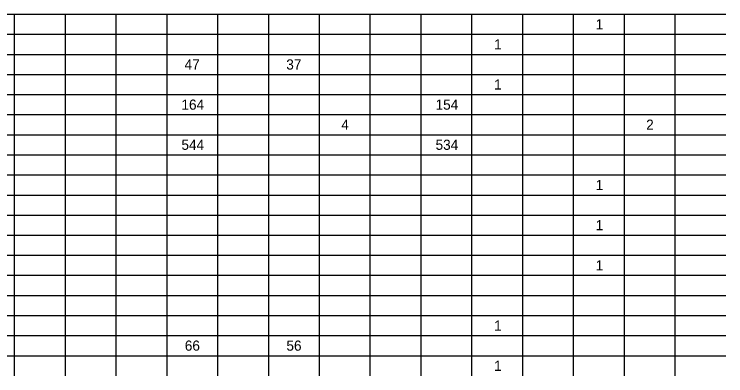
# Model space of a CAD drawing. Extents: x 0 to 34, y 0 to 22.
# Drawn here: x 16.82 to 26.95, y 10.33 to 15.49 of the extents above; entities that cross this region are included whole.
import ezdxf

# ---------------------------------------------------------------- set-up
doc = ezdxf.new("R2010")
doc.units = 0
doc.layers.add('Default', color=7, linetype='Continuous')

msp = doc.modelspace()

# ---------------------------------------------------------------- linework, layer by layer
at = {"layer": 'Default'}
for p, q in [((15.374, 15.486), (16.822, 15.486)), ((16.822, 15.486), (23.336, 15.486)), ((16.822, 15.486), (16.822, 15.199)), ((17.546, 15.486), (17.546, 15.199)), ((18.27, 15.486), (18.27, 15.199)), ((18.993, 15.486), (18.993, 15.199)), ((19.717, 15.486), (19.717, 15.199)), ((20.441, 15.486), (20.441, 15.199)), ((21.165, 15.486), (21.165, 15.199)), ((21.888, 15.486), (21.888, 15.199)), ((22.612, 15.486), (22.612, 15.199)), ((23.336, 15.486), (24.06, 15.486)), ((23.336, 15.486), (23.336, 15.199)), ((24.06, 15.486), (26.231, 15.486)), ((24.06, 15.486), (24.06, 15.199)), ((24.783, 15.486), (24.783, 15.199)), ((25.507, 15.486), (25.507, 15.199)), ((26.231, 15.486), (26.955, 15.486)), ((26.231, 15.486), (26.231, 15.199)), ((15.374, 15.199), (16.822, 15.199)), ((16.822, 15.199), (23.336, 15.199)), ((16.822, 15.199), (16.822, 14.913)), ((17.546, 15.199), (17.546, 14.913)), ((18.27, 15.199), (18.27, 14.913)), ((18.993, 15.199), (18.993, 14.913)), ((19.717, 15.199), (19.717, 14.913)), ((20.441, 15.199), (20.441, 14.913)), ((21.165, 15.199), (21.165, 14.913)), ((21.888, 15.199), (21.888, 14.913)), ((22.612, 15.199), (22.612, 14.913)), ((23.336, 15.199), (24.06, 15.199)), ((23.336, 15.199), (23.336, 14.913)), ((24.06, 15.199), (26.231, 15.199)), ((24.06, 15.199), (24.06, 14.913)), ((24.783, 15.199), (24.783, 14.913)), ((25.507, 15.199), (25.507, 14.913)), ((26.231, 15.199), (26.955, 15.199)), ((26.231, 15.199), (26.231, 14.913)), ((15.374, 14.913), (16.822, 14.913)), ((16.822, 14.913), (23.336, 14.913)), ((16.822, 14.913), (16.822, 14.626)), ((17.546, 14.913), (17.546, 14.626)), ((18.27, 14.913), (18.27, 14.626)), ((18.993, 14.913), (18.993, 14.626)), ((19.717, 14.913), (19.717, 14.626)), ((20.441, 14.913), (20.441, 14.626)), ((21.165, 14.913), (21.165, 14.626)), ((21.888, 14.913), (21.888, 14.626)), ((22.612, 14.913), (22.612, 14.626)), ((23.336, 14.913), (24.06, 14.913)), ((23.336, 14.913), (23.336, 14.626)), ((24.06, 14.913), (26.231, 14.913)), ((24.06, 14.913), (24.06, 14.626)), ((24.783, 14.913), (24.783, 14.626)), ((25.507, 14.913), (25.507, 14.626)), ((26.231, 14.913), (26.955, 14.913)), ((26.231, 14.913), (26.231, 14.626)), ((15.374, 14.626), (16.822, 14.626)), ((16.822, 14.626), (23.336, 14.626)), ((16.822, 14.626), (16.822, 14.34)), ((17.546, 14.626), (17.546, 14.34)), ((18.27, 14.626), (18.27, 14.34)), ((18.993, 14.626), (18.993, 14.34)), ((19.717, 14.626), (19.717, 14.34)), ((20.441, 14.626), (20.441, 14.34)), ((21.165, 14.626), (21.165, 14.34)), ((21.888, 14.626), (21.888, 14.34)), ((22.612, 14.626), (22.612, 14.34)), ((23.336, 14.626), (24.06, 14.626)), ((23.336, 14.626), (23.336, 14.34)), ((24.06, 14.626), (26.231, 14.626)), ((24.06, 14.626), (24.06, 14.34)), ((24.783, 14.626), (24.783, 14.34)), ((25.507, 14.626), (25.507, 14.34)), ((26.231, 14.626), (26.955, 14.626)), ((26.231, 14.626), (26.231, 14.34)), ((15.374, 14.34), (16.822, 14.34)), ((16.822, 14.34), (23.336, 14.34)), ((16.822, 14.34), (16.822, 14.054)), ((17.546, 14.34), (17.546, 14.054)), ((18.27, 14.34), (18.27, 14.054)), ((18.993, 14.34), (18.993, 14.054)), ((19.717, 14.34), (19.717, 14.054)), ((20.441, 14.34), (20.441, 14.054)), ((21.165, 14.34), (21.165, 14.054)), ((21.888, 14.34), (21.888, 14.054)), ((22.612, 14.34), (22.612, 14.054)), ((23.336, 14.34), (24.06, 14.34)), ((23.336, 14.34), (23.336, 14.054)), ((24.06, 14.34), (26.231, 14.34)), ((24.06, 14.34), (24.06, 14.054)), ((24.783, 14.34), (24.783, 14.054)), ((25.507, 14.34), (25.507, 14.054)), ((26.231, 14.34), (26.955, 14.34)), ((26.231, 14.34), (26.231, 14.054)), ((15.374, 14.054), (16.822, 14.054)), ((16.822, 14.054), (23.336, 14.054)), ((16.822, 14.054), (16.822, 13.767)), ((17.546, 14.054), (17.546, 13.767)), ((18.27, 14.054), (18.27, 13.767)), ((18.993, 14.054), (18.993, 13.767)), ((19.717, 14.054), (19.717, 13.767)), ((20.441, 14.054), (20.441, 13.767)), ((21.165, 14.054), (21.165, 13.767)), ((21.888, 14.054), (21.888, 13.767)), ((22.612, 14.054), (22.612, 13.767)), ((23.336, 14.054), (24.06, 14.054)), ((23.336, 14.054), (23.336, 13.767)), ((24.06, 14.054), (26.231, 14.054)), ((24.06, 14.054), (24.06, 13.767)), ((24.783, 14.054), (24.783, 13.767)), ((25.507, 14.054), (25.507, 13.767)), ((26.231, 14.054), (26.955, 14.054)), ((26.231, 14.054), (26.231, 13.767)), ((15.374, 13.767), (16.822, 13.767)), ((16.822, 13.767), (23.336, 13.767)), ((16.822, 13.767), (16.822, 13.481)), ((17.546, 13.767), (17.546, 13.481)), ((18.27, 13.767), (18.27, 13.481)), ((18.993, 13.767), (18.993, 13.481)), ((19.717, 13.767), (19.717, 13.481)), ((20.441, 13.767), (20.441, 13.481)), ((21.165, 13.767), (21.165, 13.481)), ((21.888, 13.767), (21.888, 13.481)), ((22.612, 13.767), (22.612, 13.481)), ((23.336, 13.767), (24.06, 13.767)), ((23.336, 13.767), (23.336, 13.481)), ((24.06, 13.767), (26.231, 13.767)), ((24.06, 13.767), (24.06, 13.481)), ((24.783, 13.767), (24.783, 13.481)), ((25.507, 13.767), (25.507, 13.481)), ((26.231, 13.767), (26.955, 13.767)), ((26.231, 13.767), (26.231, 13.481)), ((15.374, 13.481), (16.822, 13.481)), ((16.822, 13.481), (23.336, 13.481)), ((16.822, 13.481), (16.822, 13.195)), ((17.546, 13.481), (17.546, 13.195)), ((18.27, 13.481), (18.27, 13.195)), ((18.993, 13.481), (18.993, 13.195)), ((19.717, 13.481), (19.717, 13.195)), ((20.441, 13.481), (20.441, 13.195)), ((21.165, 13.481), (21.165, 13.195)), ((21.888, 13.481), (21.888, 13.195)), ((22.612, 13.481), (22.612, 13.195)), ((23.336, 13.481), (24.06, 13.481)), ((23.336, 13.481), (23.336, 13.195)), ((24.06, 13.481), (26.231, 13.481)), ((24.06, 13.481), (24.06, 13.195)), ((24.783, 13.481), (24.783, 13.195)), ((25.507, 13.481), (25.507, 13.195)), ((26.231, 13.481), (26.955, 13.481)), ((26.231, 13.481), (26.231, 13.195)), ((15.374, 13.195), (16.822, 13.195)), ((16.822, 13.195), (23.336, 13.195)), ((16.822, 13.195), (16.822, 12.908)), ((17.546, 13.195), (17.546, 12.908)), ((18.27, 13.195), (18.27, 12.908)), ((18.993, 13.195), (18.993, 12.908)), ((19.717, 13.195), (19.717, 12.908)), ((20.441, 13.195), (20.441, 12.908)), ((21.165, 13.195), (21.165, 12.908)), ((21.888, 13.195), (21.888, 12.908)), ((22.612, 13.195), (22.612, 12.908)), ((23.336, 13.195), (24.06, 13.195)), ((23.336, 13.195), (23.336, 12.908)), ((24.06, 13.195), (26.231, 13.195)), ((24.06, 13.195), (24.06, 12.908)), ((24.783, 13.195), (24.783, 12.908)), ((25.507, 13.195), (25.507, 12.908)), ((26.231, 13.195), (26.955, 13.195)), ((26.231, 13.195), (26.231, 12.908)), ((15.374, 12.908), (16.822, 12.908)), ((16.822, 12.908), (23.336, 12.908)), ((16.822, 12.908), (16.822, 12.622)), ((17.546, 12.908), (17.546, 12.622)), ((18.27, 12.908), (18.27, 12.622)), ((18.993, 12.908), (18.993, 12.622)), ((19.717, 12.908), (19.717, 12.622)), ((20.441, 12.908), (20.441, 12.622)), ((21.165, 12.908), (21.165, 12.622)), ((21.888, 12.908), (21.888, 12.622)), ((22.612, 12.908), (22.612, 12.622)), ((23.336, 12.908), (24.06, 12.908)), ((23.336, 12.908), (23.336, 12.622)), ((24.06, 12.908), (26.231, 12.908)), ((24.06, 12.908), (24.06, 12.622)), ((24.783, 12.908), (24.783, 12.622)), ((25.507, 12.908), (25.507, 12.622)), ((26.231, 12.908), (26.955, 12.908)), ((26.231, 12.908), (26.231, 12.622)), ((15.374, 12.622), (16.822, 12.622)), ((16.822, 12.622), (23.336, 12.622)), ((16.822, 12.622), (16.822, 12.335)), ((17.546, 12.622), (17.546, 12.335)), ((18.27, 12.622), (18.27, 12.335)), ((18.993, 12.622), (18.993, 12.335)), ((19.717, 12.622), (19.717, 12.335)), ((20.441, 12.622), (20.441, 12.335)), ((21.165, 12.622), (21.165, 12.335)), ((21.888, 12.622), (21.888, 12.335)), ((22.612, 12.622), (22.612, 12.335)), ((23.336, 12.622), (24.06, 12.622)), ((23.336, 12.622), (23.336, 12.335)), ((24.06, 12.622), (26.231, 12.622)), ((24.06, 12.622), (24.06, 12.335)), ((24.783, 12.622), (24.783, 12.335)), ((25.507, 12.622), (25.507, 12.335)), ((26.231, 12.622), (26.955, 12.622)), ((26.231, 12.622), (26.231, 12.335)), ((15.374, 12.335), (16.822, 12.335)), ((16.822, 12.335), (23.336, 12.335)), ((16.822, 12.335), (16.822, 12.049)), ((17.546, 12.335), (17.546, 12.049)), ((18.27, 12.335), (18.27, 12.049)), ((18.993, 12.335), (18.993, 12.049)), ((19.717, 12.335), (19.717, 12.049)), ((20.441, 12.335), (20.441, 12.049)), ((21.165, 12.335), (21.165, 12.049)), ((21.888, 12.335), (21.888, 12.049)), ((22.612, 12.335), (22.612, 12.049)), ((23.336, 12.335), (24.06, 12.335)), ((23.336, 12.335), (23.336, 12.049)), ((24.06, 12.335), (26.231, 12.335)), ((24.06, 12.335), (24.06, 12.049)), ((24.783, 12.335), (24.783, 12.049)), ((25.507, 12.335), (25.507, 12.049)), ((26.231, 12.335), (26.955, 12.335)), ((26.231, 12.335), (26.231, 12.049)), ((15.374, 12.049), (16.822, 12.049)), ((16.822, 12.049), (23.336, 12.049)), ((16.822, 12.049), (16.822, 11.763)), ((17.546, 12.049), (17.546, 11.763)), ((18.27, 12.049), (18.27, 11.763)), ((18.993, 12.049), (18.993, 11.763)), ((19.717, 12.049), (19.717, 11.763)), ((20.441, 12.049), (20.441, 11.763)), ((21.165, 12.049), (21.165, 11.763)), ((21.888, 12.049), (21.888, 11.763)), ((22.612, 12.049), (22.612, 11.763)), ((23.336, 12.049), (24.06, 12.049)), ((23.336, 12.049), (23.336, 11.763)), ((24.06, 12.049), (26.231, 12.049)), ((24.06, 12.049), (24.06, 11.763)), ((24.783, 12.049), (24.783, 11.763)), ((25.507, 12.049), (25.507, 11.763)), ((26.231, 12.049), (26.955, 12.049)), ((26.231, 12.049), (26.231, 11.763)), ((15.374, 11.763), (16.822, 11.763)), ((16.822, 11.763), (23.336, 11.763)), ((16.822, 11.763), (16.822, 11.476)), ((17.546, 11.763), (17.546, 11.476)), ((18.27, 11.763), (18.27, 11.476)), ((18.993, 11.763), (18.993, 11.476)), ((19.717, 11.763), (19.717, 11.476)), ((20.441, 11.763), (20.441, 11.476)), ((21.165, 11.763), (21.165, 11.476)), ((21.888, 11.763), (21.888, 11.476)), ((22.612, 11.763), (22.612, 11.476)), ((23.336, 11.763), (24.06, 11.763)), ((23.336, 11.763), (23.336, 11.476)), ((24.06, 11.763), (26.231, 11.763)), ((24.06, 11.763), (24.06, 11.476)), ((24.783, 11.763), (24.783, 11.476)), ((25.507, 11.763), (25.507, 11.476)), ((26.231, 11.763), (26.955, 11.763)), ((26.231, 11.763), (26.231, 11.476)), ((15.374, 11.476), (16.822, 11.476)), ((16.822, 11.476), (23.336, 11.476)), ((16.822, 11.476), (16.822, 11.19)), ((17.546, 11.476), (17.546, 11.19)), ((18.27, 11.476), (18.27, 11.19)), ((18.993, 11.476), (18.993, 11.19)), ((19.717, 11.476), (19.717, 11.19)), ((20.441, 11.476), (20.441, 11.19)), ((21.165, 11.476), (21.165, 11.19)), ((21.888, 11.476), (21.888, 11.19)), ((22.612, 11.476), (22.612, 11.19)), ((23.336, 11.476), (24.06, 11.476)), ((23.336, 11.476), (23.336, 11.19)), ((24.06, 11.476), (26.231, 11.476)), ((24.06, 11.476), (24.06, 11.19)), ((24.783, 11.476), (24.783, 11.19)), ((25.507, 11.476), (25.507, 11.19)), ((26.231, 11.476), (26.955, 11.476)), ((26.231, 11.476), (26.231, 11.19)), ((15.374, 11.19), (16.822, 11.19)), ((16.822, 11.19), (23.336, 11.19)), ((16.822, 11.19), (16.822, 10.903)), ((17.546, 11.19), (17.546, 10.903)), ((18.27, 11.19), (18.27, 10.903)), ((18.993, 11.19), (18.993, 10.903)), ((19.717, 11.19), (19.717, 10.903)), ((20.441, 11.19), (20.441, 10.903)), ((21.165, 11.19), (21.165, 10.903)), ((21.888, 11.19), (21.888, 10.903)), ((22.612, 11.19), (22.612, 10.903)), ((23.336, 11.19), (24.06, 11.19)), ((23.336, 11.19), (23.336, 10.903)), ((24.06, 11.19), (26.231, 11.19)), ((24.06, 11.19), (24.06, 10.903)), ((24.783, 11.19), (24.783, 10.903)), ((25.507, 11.19), (25.507, 10.903)), ((26.231, 11.19), (26.955, 11.19)), ((26.231, 11.19), (26.231, 10.903)), ((15.374, 10.903), (16.822, 10.903)), ((16.822, 10.903), (23.336, 10.903)), ((16.822, 10.903), (16.822, 10.617)), ((17.546, 10.903), (17.546, 10.617)), ((18.27, 10.903), (18.27, 10.617)), ((18.993, 10.903), (18.993, 10.617)), ((19.717, 10.903), (19.717, 10.617)), ((20.441, 10.903), (20.441, 10.617)), ((21.165, 10.903), (21.165, 10.617)), ((21.888, 10.903), (21.888, 10.617)), ((22.612, 10.903), (22.612, 10.617)), ((23.336, 10.903), (24.06, 10.903)), ((23.336, 10.903), (23.336, 10.617)), ((24.06, 10.903), (26.231, 10.903)), ((24.06, 10.903), (24.06, 10.617)), ((24.783, 10.903), (24.783, 10.617)), ((25.507, 10.903), (25.507, 10.617)), ((26.231, 10.903), (26.955, 10.903)), ((26.231, 10.903), (26.231, 10.617)), ((15.374, 10.617), (16.822, 10.617)), ((16.822, 10.617), (23.336, 10.617)), ((16.822, 10.617), (16.822, 10.331)), ((17.546, 10.617), (17.546, 10.331)), ((18.27, 10.617), (18.27, 10.331)), ((18.993, 10.617), (18.993, 10.331)), ((19.717, 10.617), (19.717, 10.331)), ((20.441, 10.617), (20.441, 10.331)), ((21.165, 10.617), (21.165, 10.331)), ((21.888, 10.617), (21.888, 10.331)), ((22.612, 10.617), (22.612, 10.331)), ((23.336, 10.617), (24.06, 10.617)), ((23.336, 10.617), (23.336, 10.331)), ((24.06, 10.617), (26.231, 10.617)), ((24.06, 10.617), (24.06, 10.331)), ((24.783, 10.617), (24.783, 10.331)), ((25.507, 10.617), (25.507, 10.331)), ((26.231, 10.617), (26.955, 10.617)), ((26.231, 10.617), (26.231, 10.331))]:
    msp.add_line(p, q, dxfattribs=at)

# ---------------------------------------------------------------- texts
for s, height, p in [('1', 0.145, (25.103, 15.27)), ('1', 0.145, (23.656, 14.984)), ('47', 0.1449, (19.248, 14.697)), ('37', 0.1449, (20.696, 14.697)), ('1', 0.145, (23.656, 14.411)), ('164', 0.1449, (19.203, 14.124)), ('154', 0.1449, (22.822, 14.124)), ('2', 0.145, (25.821, 13.838)), ('4', 0.145, (21.479, 13.838)), ('544', 0.1449, (19.203, 13.552)), ('534', 0.1449, (22.822, 13.552)), ('1', 0.145, (25.103, 12.979)), ('1', 0.145, (25.103, 12.406)), ('1', 0.145, (25.103, 11.833)), ('1', 0.145, (23.656, 10.974)), ('66', 0.1449, (19.251, 10.688)), ('56', 0.1449, (20.698, 10.688)), ('1', 0.145, (23.656, 10.401))]:
    msp.add_text(s, height=height, dxfattribs=at).set_placement(p)

doc.saveas('drawing.dxf')
